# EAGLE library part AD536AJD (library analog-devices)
ANALOG DEVICES
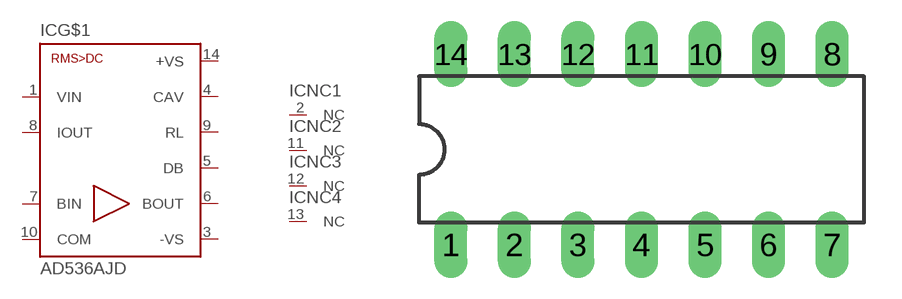
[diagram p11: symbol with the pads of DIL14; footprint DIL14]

Designator prefix IC; gates G$1=AD536 NC1=NC NC2=NC NC3=NC NC4=NC

## AD536AJD (MF: ALTERA CORPORATION; MPN: AD536AJD; OC_FARNELL: 405358; OC_NEWARK: 05F6939)  [DIL14]
1  G$1:VIN  in
2  NC1:NC  nc
3  G$1:-VS  pwr
4  G$1:CAV  out
5  G$1:DB  out
6  G$1:BOUT  out
7  G$1:BIN  in
8  G$1:IOUT  out
9  G$1:RL  pas
10  G$1:COM  pwr
11  NC2:NC  nc
12  NC3:NC  nc
13  NC4:NC  nc
14  G$1:+VS  pwr

## Footprint DIL14 (pad centres in mm)
Dual In Line Package
drill 0.813 long: 1 -7.62,-3.81; 2 -5.08,-3.81; 3 -2.54,-3.81; 4 0,-3.81; 5 2.54,-3.81; 6 5.08,-3.81; 7 7.62,-3.81; 8 7.62,3.81; 9 5.08,3.81; 10 2.54,3.81; 11 0,3.81; 12 -2.54,3.81; 13 -5.08,3.81; 14 -7.62,3.81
